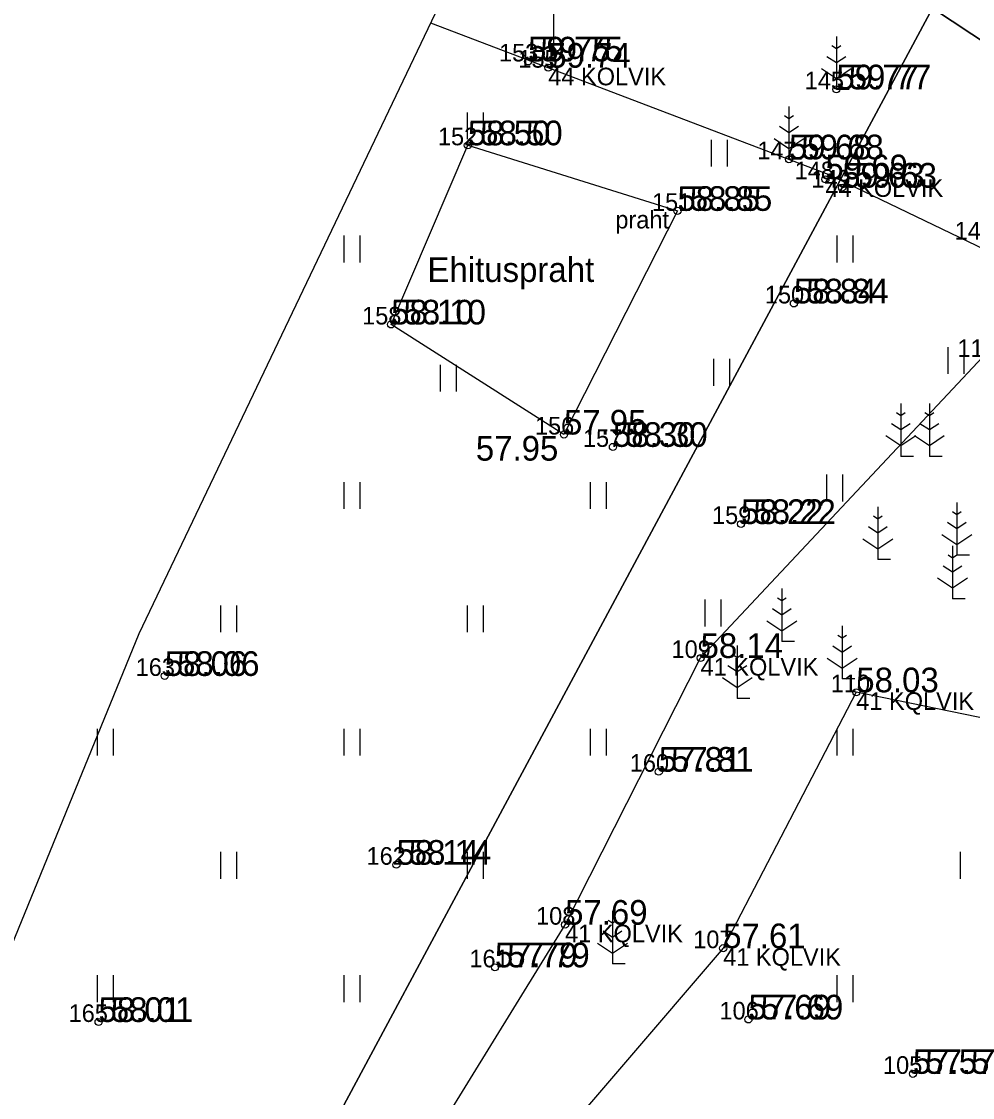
# Model space of a CAD drawing. Extents: x 640891 to 641083, y 6456526 to 6456669.
# Drawn here: x 640934.89 to 640961.9, y 6456618.41 to 6456648.96 of the extents above; entities that cross this region are included whole.
import ezdxf

# ---------------------------------------------------------------- set-up
doc = ezdxf.new("R2010")
doc.units = 0
for name, color, linetype in [('100koma2', 7, 'Continuous'), ('HALJASTUS', 7, 'Continuous'), ('KORGUS', 7, 'Continuous'), ('MOOTKORG', 7, 'Continuous'), ('MOOTMPUNKT', 7, 'Continuous'), ('MOOTNR', 7, 'Continuous'), ('MOOTPIIR', 7, 'Continuous'), ('PIIR', 7, 'Continuous'), ('PUU', 7, 'Continuous'), ('VORK', 7, 'Continuous')]:
    doc.layers.add(name, color=color, linetype=linetype)

msp = doc.modelspace()

# ---------------------------------------------------------------- linework, layer by layer
at = {"layer": 'HALJASTUS'}
for p, q in [((640947.545, 6456646.381), (640947.545, 6456645.619)), ((640948, 6456646.381), (640948, 6456645.619)), ((640954.474, 6456645.605), (640954.474, 6456644.844)), ((640954.929, 6456645.605), (640954.929, 6456644.844)), ((640944.045, 6456642.881), (640944.045, 6456642.119)), ((640944.5, 6456642.881), (640944.5, 6456642.119)), ((640958.045, 6456642.881), (640958.045, 6456642.119)), ((640958.5, 6456642.881), (640958.5, 6456642.119)), ((640961.197, 6456639.718), (640961.197, 6456638.957)), ((640961.652, 6456639.718), (640961.652, 6456638.957)), ((640946.778, 6456639.216), (640946.778, 6456638.454)), ((640947.233, 6456639.216), (640947.233, 6456638.454)), ((640954.545, 6456639.381), (640954.545, 6456638.619)), ((640955, 6456639.381), (640955, 6456638.619)), ((640957.75, 6456636.095), (640957.75, 6456635.334)), ((640958.205, 6456636.095), (640958.205, 6456635.334)), ((640944.045, 6456635.881), (640944.045, 6456635.119)), ((640944.5, 6456635.881), (640944.5, 6456635.119)), ((640951.045, 6456635.881), (640951.045, 6456635.119)), ((640951.5, 6456635.881), (640951.5, 6456635.119)), ((640940.545, 6456632.381), (640940.545, 6456631.619)), ((640941, 6456632.381), (640941, 6456631.619)), ((640947.545, 6456632.381), (640947.545, 6456631.619)), ((640948, 6456632.381), (640948, 6456631.619)), ((640954.294, 6456632.546), (640954.294, 6456631.784)), ((640954.749, 6456632.546), (640954.749, 6456631.784)), ((640937.045, 6456628.881), (640937.045, 6456628.119)), ((640937.5, 6456628.881), (640937.5, 6456628.119)), ((640944.045, 6456628.881), (640944.045, 6456628.119)), ((640944.5, 6456628.881), (640944.5, 6456628.119)), ((640951.045, 6456628.881), (640951.045, 6456628.119)), ((640951.5, 6456628.881), (640951.5, 6456628.119)), ((640958.045, 6456628.881), (640958.045, 6456628.119)), ((640958.5, 6456628.881), (640958.5, 6456628.119)), ((640940.545, 6456625.381), (640940.545, 6456624.619)), ((640941, 6456625.381), (640941, 6456624.619)), ((640947.545, 6456625.381), (640947.545, 6456624.619)), ((640948, 6456625.381), (640948, 6456624.619)), ((640961.545, 6456625.381), (640961.545, 6456624.619)), ((640937.045, 6456621.881), (640937.045, 6456621.119)), ((640937.5, 6456621.881), (640937.5, 6456621.119)), ((640944.045, 6456621.881), (640944.045, 6456621.119)), ((640944.5, 6456621.881), (640944.5, 6456621.119)), ((640958.045, 6456621.881), (640958.045, 6456621.119)), ((640958.5, 6456621.881), (640958.5, 6456621.119))]:
    msp.add_line(p, q, dxfattribs=at)
for points in [[(640946.505, 6456648.924), (640957.822, 6456644.615), (640966.207, 6456640.588), (640973.066, 6456642.422), (640986.679, 6456634.293)], [(640953.521, 6456643.585), (640950.298, 6456637.234), (640945.39, 6456640.359), (640947.568, 6456645.447), (640953.521, 6456643.585)], [(640940.859, 6456588.363), (640936.098, 6456589.959), (640937.267, 6456594.734), (640939.119, 6456600.434), (640944.153, 6456613.282), (640950.33, 6456623.315), (640954.177, 6456630.888), (640962.196, 6456639.436), (640963.998, 6456638.677), (640968.745, 6456632.01), (640966.503, 6456625.352), (640963.655, 6456626.075), (640962.794, 6456629.058), (640958.598, 6456629.914), (640954.818, 6456622.648), (640946.439, 6456612.875), (640948.12, 6456609.151), (640945.862, 6456604.895), (640949.763, 6456601.734), (640945.05, 6456592.964), (640940.483, 6456588.68)]]:
    msp.add_lwpolyline(points, dxfattribs=at)
at = {"layer": 'KORGUS'}
for centre in [(640949.278, 6456647.827), (640958.033, 6456647.035), (640947.568, 6456645.447), (640956.687, 6456645.048), (640958.197, 6456644.244), (640953.521, 6456643.585), (640956.827, 6456640.956), (640945.39, 6456640.359), (640950.298, 6456637.234), (640951.686, 6456636.883), (640955.326, 6456634.693), (640938.96, 6456630.379), (640952.991, 6456627.659), (640945.541, 6456625.017), (640948.337, 6456622.105), (640937.081, 6456620.553), (640955.537, 6456620.624), (640960.207, 6456619.08)]:
    msp.add_circle(centre, 0.1, dxfattribs=at)
at = {"layer": 'MOOTMPUNKT'}
for centre in [(640949.278, 6456647.827), (640949.852, 6456647.65), (640958.033, 6456647.035), (640947.568, 6456645.447), (640956.687, 6456645.048), (640957.722, 6456644.481), (640958.197, 6456644.244), (640953.521, 6456643.585), (640956.827, 6456640.956), (640945.39, 6456640.359), (640950.298, 6456637.234), (640951.686, 6456636.883), (640955.326, 6456634.693), (640954.177, 6456630.888), (640938.96, 6456630.379), (640958.598, 6456629.914), (640952.991, 6456627.659), (640945.541, 6456625.017), (640950.33, 6456623.315), (640954.818, 6456622.648), (640948.337, 6456622.105), (640937.081, 6456620.553), (640955.537, 6456620.624), (640960.207, 6456619.08)]:
    msp.add_circle(centre, 0.1, dxfattribs=at)
at = {"layer": 'MOOTPIIR'}
msp.add_lwpolyline([(640924.706, 6456598.502), (640938.233, 6456631.58), (640948.873, 6456653.866), (640953.873, 6456657.504), (640964.983, 6456662.356), (640986.497, 6456646.235), (640995.587, 6456643.81), (640989.565, 6456627.418), (640994.744, 6456619.938), (640993.953, 6456602.696)], dxfattribs=at)
at = {"layer": 'PIIR'}
msp.add_lwpolyline([(641039.59, 6456660.086), (641000.58, 6456623), (640985.89, 6456632.73), (640960.76, 6456649.34), (640935.64, 6456665.95), (640931.367, 6456668.776)], dxfattribs=at)
for points in [[(640930.79, 6456593.51), (640904.36, 6456607.7), (640935.64, 6456665.95), (640960.76, 6456649.34)], [(640957.22, 6456579.32), (640930.79, 6456593.51), (640960.76, 6456649.34), (640985.89, 6456632.73)]]:
    msp.add_lwpolyline(points, close=True, dxfattribs=at)
at = {"layer": 'PUU'}
for p, q in [((640958.033, 6456648.185), (640957.908, 6456648.268)), ((640958.033, 6456648.535), (640958.033, 6456647.035)), ((640958.157, 6456648.268), (640958.033, 6456648.185)), ((640958.033, 6456647.785), (640957.766, 6456647.963)), ((640958.299, 6456647.963), (640958.033, 6456647.785)), ((640957.608, 6456647.624), (640958.033, 6456647.342)), ((640958.033, 6456647.342), (640958.457, 6456647.624)), ((640958.393, 6456647.035), (640958.033, 6456647.035)), ((640956.687, 6456646.548), (640956.687, 6456645.048)), ((640956.687, 6456646.198), (640956.563, 6456646.281)), ((640956.812, 6456646.281), (640956.687, 6456646.198)), ((640956.687, 6456645.798), (640956.421, 6456645.976)), ((640956.954, 6456645.976), (640956.687, 6456645.798)), ((640956.263, 6456645.637), (640956.687, 6456645.354)), ((640956.687, 6456645.354), (640957.112, 6456645.637)), ((640957.047, 6456645.048), (640956.687, 6456645.048)), ((640959.865, 6456638.113), (640959.865, 6456636.613)), ((640960.673, 6456638.113), (640960.673, 6456636.613)), ((640959.865, 6456637.763), (640959.741, 6456637.846)), ((640959.99, 6456637.846), (640959.865, 6456637.763)), ((640960.673, 6456637.763), (640960.549, 6456637.846)), ((640960.798, 6456637.846), (640960.673, 6456637.763)), ((640959.865, 6456637.363), (640959.599, 6456637.541)), ((640960.132, 6456637.541), (640959.865, 6456637.363)), ((640960.673, 6456637.363), (640960.407, 6456637.541)), ((640960.94, 6456637.541), (640960.673, 6456637.363)), ((640959.441, 6456637.203), (640959.865, 6456636.92)), ((640959.865, 6456636.92), (640960.29, 6456637.203)), ((640960.249, 6456637.203), (640960.673, 6456636.92)), ((640960.673, 6456636.92), (640961.098, 6456637.203)), ((640960.225, 6456636.613), (640959.865, 6456636.613)), ((640961.033, 6456636.613), (640960.673, 6456636.613)), ((640959.209, 6456635.182), (640959.209, 6456633.682)), ((640961.454, 6456635.304), (640961.454, 6456633.804)), ((640959.209, 6456634.832), (640959.084, 6456634.915)), ((640959.333, 6456634.915), (640959.209, 6456634.832)), ((640961.454, 6456634.954), (640961.33, 6456635.037)), ((640961.579, 6456635.037), (640961.454, 6456634.954)), ((640959.209, 6456634.432), (640958.942, 6456634.61)), ((640959.475, 6456634.61), (640959.209, 6456634.432)), ((640961.454, 6456634.554), (640961.188, 6456634.731)), ((640961.721, 6456634.731), (640961.454, 6456634.554)), ((640958.785, 6456634.272), (640959.209, 6456633.989)), ((640959.209, 6456633.989), (640959.633, 6456634.272)), ((640961.03, 6456634.393), (640961.454, 6456634.11)), ((640961.454, 6456634.11), (640961.879, 6456634.393)), ((640961.33, 6456634.071), (640961.33, 6456632.571)), ((640959.569, 6456633.682), (640959.209, 6456633.682)), ((640961.33, 6456633.721), (640961.206, 6456633.804)), ((640961.454, 6456633.804), (640961.33, 6456633.721)), ((640961.814, 6456633.804), (640961.454, 6456633.804)), ((640961.33, 6456633.321), (640961.063, 6456633.498)), ((640961.597, 6456633.498), (640961.33, 6456633.321)), ((640960.906, 6456633.16), (640961.33, 6456632.877)), ((640961.33, 6456632.877), (640961.754, 6456633.16)), ((640956.482, 6456632.858), (640956.482, 6456631.358)), ((640956.482, 6456632.508), (640956.357, 6456632.591)), ((640956.606, 6456632.591), (640956.482, 6456632.508)), ((640961.69, 6456632.571), (640961.33, 6456632.571)), ((640956.482, 6456632.108), (640956.215, 6456632.286)), ((640956.748, 6456632.286), (640956.482, 6456632.108)), ((640956.058, 6456631.947), (640956.482, 6456631.664)), ((640956.482, 6456631.664), (640956.906, 6456631.947)), ((640958.199, 6456631.797), (640958.199, 6456630.297)), ((640958.199, 6456631.447), (640958.074, 6456631.53)), ((640958.323, 6456631.53), (640958.199, 6456631.447)), ((640955.219, 6456631.241), (640955.219, 6456629.741)), ((640956.842, 6456631.358), (640956.482, 6456631.358)), ((640958.199, 6456631.047), (640957.932, 6456631.224)), ((640958.465, 6456631.224), (640958.199, 6456631.047)), ((640955.219, 6456630.891), (640955.095, 6456630.974)), ((640955.344, 6456630.974), (640955.219, 6456630.891)), ((640957.775, 6456630.886), (640958.199, 6456630.603)), ((640958.199, 6456630.603), (640958.623, 6456630.886)), ((640955.219, 6456630.491), (640954.953, 6456630.669)), ((640955.486, 6456630.669), (640955.219, 6456630.491)), ((640954.795, 6456630.33), (640955.219, 6456630.047)), ((640955.219, 6456630.047), (640955.644, 6456630.33)), ((640958.559, 6456630.297), (640958.199, 6456630.297)), ((640955.579, 6456629.741), (640955.219, 6456629.741)), ((640951.677, 6456623.704), (640951.677, 6456622.204)), ((640951.677, 6456623.354), (640951.553, 6456623.437)), ((640951.801, 6456623.437), (640951.677, 6456623.354)), ((640951.677, 6456622.954), (640951.41, 6456623.132)), ((640951.944, 6456623.132), (640951.677, 6456622.954)), ((640951.253, 6456622.793), (640951.677, 6456622.51)), ((640951.677, 6456622.51), (640952.101, 6456622.793)), ((640952.037, 6456622.204), (640951.677, 6456622.204))]:
    msp.add_line(p, q, dxfattribs=at)
at = {"layer": 'VORK'}
msp.add_line((640950, 6456652), (640950, 6456648), dxfattribs=at)

# ---------------------------------------------------------------- texts
at = {"layer": '100koma2'}
for s, p in [('44 KOLVIK', (640949.852, 6456647.15)), ('44 KOLVIK', (640957.722, 6456643.981)), ('praht', (640951.756, 6456643.085)), ('41 KQLVIK', (640954.177, 6456630.388)), ('41 KQLVIK', (640958.598, 6456629.414)), ('41 KQLVIK', (640950.33, 6456622.815)), ('41 KQLVIK', (640954.818, 6456622.148))]:
    msp.add_text(s, height=0.5, dxfattribs=at).set_placement(p)
at = {"layer": 'HALJASTUS'}
msp.add_text('Ehituspraht', height=0.7, dxfattribs=at).set_placement((640946.421, 6456641.566))
at = {"layer": 'KORGUS'}
for s, p in [('59.75', (640949.628, 6456647.827)), ('59.77', (640958.383, 6456647.035)), ('58.50', (640947.918, 6456645.447)), ('59.68', (640957.037, 6456645.048)), ('59.63', (640958.547, 6456644.244)), ('58.85', (640953.871, 6456643.585)), ('58.84', (640957.177, 6456640.956)), ('58.10', (640945.74, 6456640.359)), ('58.30', (640952.036, 6456636.883)), ('57.95', (640947.795, 6456636.492)), ('58.22', (640955.676, 6456634.693)), ('58.06', (640939.31, 6456630.379)), ('57.81', (640953.341, 6456627.659)), ('58.14', (640945.891, 6456625.017)), ('57.79', (640948.687, 6456622.105)), ('58.01', (640937.431, 6456620.553)), ('57.69', (640955.887, 6456620.624)), ('57.57', (640960.557, 6456619.08))]:
    msp.add_text(s, height=0.7, dxfattribs=at).set_placement(p)
at = {"layer": 'MOOTKORG'}
for s, p in [('59.75', (640949.278, 6456647.827)), ('59.74', (640949.852, 6456647.65)), ('59.77', (640958.033, 6456647.035)), ('58.50', (640947.568, 6456645.447)), ('59.68', (640956.687, 6456645.048)), ('59.69', (640957.722, 6456644.481)), ('59.63', (640958.197, 6456644.244)), ('58.85', (640953.521, 6456643.585)), ('58.84', (640956.827, 6456640.956)), ('58.10', (640945.39, 6456640.359)), ('57.95', (640950.298, 6456637.234)), ('58.30', (640951.686, 6456636.883)), ('58.22', (640955.326, 6456634.693)), ('58.14', (640954.177, 6456630.888)), ('58.06', (640938.96, 6456630.379)), ('58.03', (640958.598, 6456629.914)), ('57.81', (640952.991, 6456627.659)), ('58.14', (640945.541, 6456625.017)), ('57.69', (640950.33, 6456623.315)), ('57.61', (640954.818, 6456622.648)), ('57.79', (640948.337, 6456622.105)), ('58.01', (640937.081, 6456620.553)), ('57.69', (640955.537, 6456620.624)), ('57.57', (640960.207, 6456619.08))]:
    msp.add_text(s, height=0.7, dxfattribs=at).set_placement(p)
at = {"layer": 'MOOTNR'}
for s, p in [('153', (640948.453, 6456647.827)), ('155', (640949.002, 6456647.65)), ('145', (640957.133, 6456647.035)), ('152', (640946.718, 6456645.447)), ('147', (640955.787, 6456645.048)), ('148', (640956.847, 6456644.481)), ('149', (640957.322, 6456644.244)), ('151', (640952.796, 6456643.585)), ('144', (640961.392, 6456642.77)), ('150', (640956.002, 6456640.956)), ('158', (640944.565, 6456640.359)), ('116', (640961.471, 6456639.436)), ('156', (640949.473, 6456637.234)), ('157', (640950.836, 6456636.883)), ('159', (640954.501, 6456634.693)), ('109', (640953.352, 6456630.888)), ('163', (640938.135, 6456630.379)), ('110', (640957.873, 6456629.914)), ('160', (640952.166, 6456627.659)), ('162', (640944.691, 6456625.017)), ('108', (640949.505, 6456623.315)), ('107', (640953.968, 6456622.648)), ('161', (640947.612, 6456622.105)), ('165', (640936.231, 6456620.553)), ('106', (640954.713, 6456620.624)), ('105', (640959.357, 6456619.08))]:
    msp.add_text(s, height=0.5, dxfattribs=at).set_placement(p)

doc.saveas('drawing.dxf')
